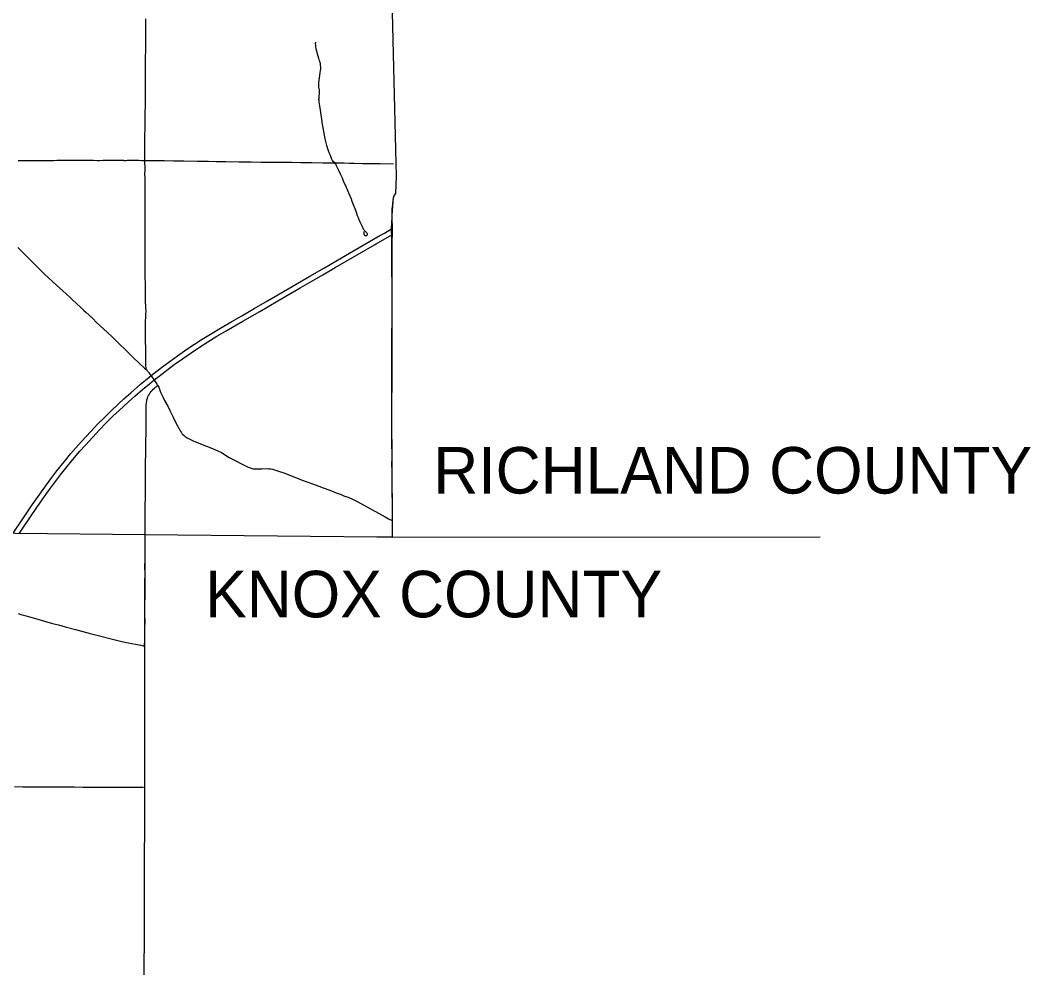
# Model space of a CAD drawing. Extents: x 9078 to 9739, y 4248 to 4966.
# Drawn here: x 9630.7 to 9739.1, y 4597.9 to 4699.7 of the extents above; entities that cross this region are included whole.
import ezdxf

# ---------------------------------------------------------------- set-up
doc = ezdxf.new("R2010")
doc.units = 0
for name, color, linetype in [('GM_X_Adjacent_County', 7, 'Continuous'), ('GM_X_Adjacent_County_Text', 7, 'Continuous'), ('GM_X_County', 7, 'Continuous'), ('GM_X_County_Road', 7, 'Continuous'), ('GM_X_Interstate_Route', 7, 'Continuous'), ('GM_X_Township', 7, 'Continuous'), ('GM_X_Township_Road', 7, 'Continuous')]:
    doc.layers.add(name, color=color, linetype=linetype)

msp = doc.modelspace()

# ---------------------------------------------------------------- linework, layer by layer
at = {"layer": 'GM_X_Adjacent_County'}
msp.add_line((9670.61, 4644.14), (9716.53, 4644.18), dxfattribs=at)
at = {"layer": 'GM_X_County'}
msp.add_lwpolyline([(9670.33, 4710.79), (9670.98, 4684.3), (9671.01, 4682.95), (9670.94, 4681.07), (9670.82, 4680.88), (9670.7, 4680.56), (9670.67, 4680.2), (9670.56, 4678.73), (9670.58, 4676.97), (9670.57, 4675.69), (9670.54, 4657.57), (9670.61, 4645.99), (9670.61, 4644.14), (9668.95, 4644.16), (9644.05, 4644.41), (9644.05, 4642.22), (9644.03, 4632.54), (9644.01, 4617.33), (9643.94, 4593.51)], dxfattribs=at)
at = {"layer": 'GM_X_County_Road'}
for points in [[(9644.29, 4662.08), (9644.26, 4662.12), (9644.23, 4662.19), (9644.2, 4662.27), (9644.19, 4662.36), (9644.17, 4662.52), (9644.15, 4663.02), (9644.16, 4663.43), (9644.16, 4663.92), (9644.15, 4664.41), (9644.11, 4665.23), (9644.11, 4665.64), (9644.12, 4666.05), (9644.14, 4666.71), (9644.14, 4667.03), (9644.17, 4668.08), (9644.18, 4668.4), (9644.16, 4668.81), (9644.12, 4669.55), (9644.12, 4669.88), (9644.12, 4670.29), (9644.13, 4670.78), (9644.12, 4671.44), (9644.1, 4672.01), (9644.1, 4672.58), (9644.08, 4673.49), (9644.08, 4673.99), (9644.09, 4674.72), (9644.09, 4675.13), (9644.1, 4675.86), (9644.1, 4676.85), (9644.1, 4677.26), (9644.08, 4678.08), (9644.08, 4678.49), (9644.08, 4679.06), (9644.09, 4679.39), (9644.09, 4679.63), (9644.08, 4680.28), (9644.08, 4680.53), (9644.07, 4680.94), (9644.07, 4681.26), (9644.08, 4681.69), (9644.07, 4681.99), (9644.07, 4682.42), (9644.07, 4682.74), (9644.06, 4683.09), (9644.07, 4683.56), (9644.07, 4683.96), (9644.06, 4684.29), (9644.06, 4684.61)], [(9645.42, 4660.46), (9645.39, 4660.52), (9645.37, 4660.59), (9645.33, 4660.66), (9645.2, 4660.87), (9645.07, 4661.05), (9645.01, 4661.13), (9644.73, 4661.5), (9644.51, 4661.78), (9644.35, 4661.98), (9644.31, 4662.04), (9644.29, 4662.08)], [(9644.08, 4644.3), (9644.1, 4645.54), (9644.09, 4646.2), (9644.1, 4647.59), (9644.12, 4648.33), (9644.12, 4649.07), (9644.13, 4649.89), (9644.13, 4650.38), (9644.14, 4650.79), (9644.13, 4651.45), (9644.14, 4652.18), (9644.15, 4653.08), (9644.16, 4653.9), (9644.17, 4654.56), (9644.18, 4655.22), (9644.19, 4656.04), (9644.18, 4656.86), (9644.18, 4657.35), (9644.19, 4658.01), (9644.2, 4658.34), (9644.22, 4658.58), (9644.25, 4658.75), (9644.28, 4658.91), (9644.32, 4659.07), (9644.38, 4659.23), (9644.45, 4659.38), (9644.54, 4659.52), (9644.63, 4659.66), (9644.73, 4659.79), (9644.84, 4659.91), (9644.96, 4660.03), (9645.08, 4660.14), (9645.21, 4660.24), (9645.27, 4660.29), (9645.34, 4660.34), (9645.38, 4660.38), (9645.42, 4660.46)], [(9644.03, 4632.46), (9644.04, 4633.11), (9644.04, 4633.76), (9644.06, 4634.49), (9644.07, 4634.98), (9644.06, 4635.88), (9644.06, 4636.62), (9644.06, 4637.44), (9644.06, 4638.74), (9644.06, 4639.23), (9644.07, 4640.29), (9644.06, 4640.95), (9644.07, 4641.77), (9644.07, 4642.34), (9644.08, 4642.99), (9644.08, 4643.81), (9644.08, 4644.3)], [(9630.45, 4635.97), (9630.76, 4635.86), (9631.3, 4635.69), (9632.56, 4635.33), (9633.27, 4635.12), (9634.14, 4634.89), (9634.78, 4634.73), (9635.49, 4634.53), (9636.6, 4634.23), (9637.39, 4634.02), (9638.19, 4633.82), (9639.06, 4633.58), (9640.72, 4633.15), (9641.44, 4632.98), (9642.25, 4632.82), (9643.05, 4632.67), (9643.62, 4632.56), (9644.03, 4632.46)]]:
    msp.add_lwpolyline(points, dxfattribs=at)
at = {"layer": 'GM_X_Interstate_Route'}
for points in [[(9629.92, 4644.59), (9630.96, 4646.12), (9631.97, 4647.62), (9632.95, 4649.03), (9633.48, 4649.77), (9634.07, 4650.56), (9634.62, 4651.27), (9635.44, 4652.29), (9636.12, 4653.12), (9636.65, 4653.74), (9637.25, 4654.41), (9638.25, 4655.5), (9638.98, 4656.27), (9639.67, 4656.98), (9640.37, 4657.66), (9641.21, 4658.46), (9641.81, 4659.01), (9642.55, 4659.66), (9643.6, 4660.57), (9644.3, 4661.15), (9644.73, 4661.5), (9645.06, 4661.77), (9645.84, 4662.37), (9646.76, 4663.05), (9647.56, 4663.63), (9648.57, 4664.33), (9649.39, 4664.88), (9650.22, 4665.41), (9651.26, 4666.06), (9652.11, 4666.56), (9653.39, 4667.3), (9654.45, 4667.92), (9655.8, 4668.7), (9657.22, 4669.52), (9659.42, 4670.8), (9661.76, 4672.16), (9663.32, 4673.07), (9665.16, 4674.14), (9667.5, 4675.5), (9669.28, 4676.53), (9669.78, 4676.81), (9670.54, 4677.25)], [(9668.7, 4675.54), (9668.89, 4675.65), (9670.55, 4676.61)], [(9661.98, 4671.64), (9663.14, 4672.31), (9664.49, 4673.09), (9666.83, 4674.46), (9668.7, 4675.54)], [(9630.6, 4644.58), (9631.03, 4645.21), (9632.45, 4647.32), (9633.1, 4648.26), (9633.72, 4649.14), (9634.35, 4649.99), (9635, 4650.84), (9635.56, 4651.55), (9636.34, 4652.5), (9637.08, 4653.38), (9637.63, 4653.99), (9638.46, 4654.9), (9639.19, 4655.68), (9639.87, 4656.38), (9640.63, 4657.13), (9641.29, 4657.75), (9642.31, 4658.7), (9642.99, 4659.3), (9643.79, 4660), (9644.55, 4660.63), (9645.07, 4661.05), (9645.58, 4661.45), (9646.22, 4661.95), (9647.21, 4662.68), (9648.08, 4663.31), (9649.02, 4663.96), (9649.91, 4664.55), (9650.81, 4665.12), (9651.79, 4665.72), (9652.78, 4666.3), (9654.56, 4667.33), (9656.4, 4668.4), (9658.32, 4669.51), (9660.73, 4670.91), (9661.98, 4671.64)]]:
    msp.add_lwpolyline(points, dxfattribs=at)
at = {"layer": 'GM_X_Township'}
msp.add_lwpolyline([(9644.05, 4644.41), (9630.13, 4644.53), (9617.44, 4644.64), (9617.14, 4644.7), (9600.03, 4645.01), (9585.46, 4645.17), (9576.58, 4645.16)], dxfattribs=at)
at = {"layer": 'GM_X_Township_Road'}
for points in [[(9644.06, 4684.61), (9644.06, 4685.55), (9644.06, 4685.98), (9644.05, 4686.4), (9644.06, 4687.36), (9644.08, 4688.01), (9644.08, 4688.42), (9644.09, 4688.99), (9644.09, 4689.32), (9644.1, 4689.89), (9644.11, 4690.3), (9644.11, 4690.87), (9644.12, 4692.18), (9644.13, 4693.17), (9644.14, 4693.82), (9644.13, 4694.56), (9644.14, 4695.46), (9644.15, 4696.61), (9644.16, 4697.51), (9644.15, 4698.25), (9644.15, 4699.23), (9644.15, 4699.8)], [(9664.43, 4684.34), (9664.28, 4684.49), (9664.2, 4684.6), (9664.09, 4684.82), (9663.96, 4685.12), (9663.87, 4685.35), (9663.75, 4685.65), (9663.64, 4685.96), (9663.57, 4686.2), (9663.53, 4686.36), (9663.42, 4686.92), (9663.34, 4687.32), (9663.26, 4687.72), (9663.18, 4688.12), (9663.13, 4688.45), (9663.08, 4688.77), (9662.98, 4689.5), (9662.92, 4689.99), (9662.83, 4690.48), (9662.77, 4690.88), (9662.75, 4691.04), (9662.74, 4691.14), (9662.75, 4691.25), (9662.77, 4691.53), (9662.8, 4691.78), (9662.81, 4691.94), (9662.8, 4692.1), (9662.78, 4692.17), (9662.72, 4692.48), (9662.72, 4692.73), (9662.73, 4692.89), (9662.73, 4692.97), (9662.75, 4693.22), (9662.78, 4693.46), (9662.82, 4693.71), (9662.88, 4694.03), (9662.92, 4694.27), (9662.93, 4694.44), (9662.93, 4694.6), (9662.91, 4694.85), (9662.89, 4695.01), (9662.87, 4695.09), (9662.82, 4695.25), (9662.77, 4695.4), (9662.72, 4695.55), (9662.65, 4695.79), (9662.58, 4696.02), (9662.54, 4696.18), (9662.45, 4696.57), (9662.41, 4696.81), (9662.39, 4696.97), (9662.38, 4697.13), (9662.39, 4697.29)], [(9630.47, 4684.59), (9630.88, 4684.6), (9631.2, 4684.6), (9631.44, 4684.59), (9631.77, 4684.6), (9632.42, 4684.61), (9632.58, 4684.61), (9632.91, 4684.61), (9633.07, 4684.61), (9633.48, 4684.61), (9633.8, 4684.61), (9634.05, 4684.61), (9634.29, 4684.61), (9634.62, 4684.62), (9634.95, 4684.63), (9635.76, 4684.63), (9636.17, 4684.64), (9636.58, 4684.64), (9636.99, 4684.64), (9638.14, 4684.62), (9638.54, 4684.62), (9638.95, 4684.61), (9639.2, 4684.61), (9639.53, 4684.62), (9639.85, 4684.62), (9640.01, 4684.62), (9640.26, 4684.63), (9640.42, 4684.63), (9640.76, 4684.62), (9641.26, 4684.63), (9641.61, 4684.63), (9641.76, 4684.62), (9641.83, 4684.61), (9641.95, 4684.61), (9642.01, 4684.61), (9642.14, 4684.62), (9642.42, 4684.62), (9643.03, 4684.62), (9643.4, 4684.62), (9643.74, 4684.61), (9643.99, 4684.6), (9644.06, 4684.61)], [(9644.06, 4684.61), (9644.4, 4684.61), (9644.73, 4684.61), (9645.3, 4684.6), (9645.71, 4684.59), (9646.12, 4684.59), (9647.18, 4684.57), (9648.25, 4684.55), (9649.72, 4684.53), (9650.38, 4684.52), (9650.87, 4684.52), (9651.69, 4684.5), (9652.75, 4684.48), (9654.15, 4684.46), (9655.46, 4684.44), (9656.52, 4684.42), (9657.18, 4684.43), (9657.84, 4684.42), (9658.49, 4684.41), (9659.15, 4684.41), (9659.8, 4684.4), (9660.78, 4684.39), (9661.27, 4684.38), (9661.92, 4684.37), (9663.15, 4684.35), (9663.81, 4684.34), (9664.43, 4684.34)], [(9667.57, 4676.99), (9667.57, 4676.86), (9667.56, 4676.78), (9667.57, 4676.7), (9667.58, 4676.66), (9667.6, 4676.62), (9667.62, 4676.59), (9667.66, 4676.56), (9667.71, 4676.54), (9667.76, 4676.53), (9667.8, 4676.53), (9667.84, 4676.54), (9667.87, 4676.56), (9667.9, 4676.59), (9667.91, 4676.62), (9667.93, 4676.65), (9667.94, 4676.69), (9667.93, 4676.73), (9667.91, 4676.77), (9667.87, 4676.84), (9667.82, 4676.9), (9667.69, 4677.01), (9667.64, 4677.07), (9667.58, 4677.13), (9667.54, 4677.2), (9667.5, 4677.27), (9667.47, 4677.33), (9667.4, 4677.47), (9667.34, 4677.62), (9667.27, 4677.77), (9667.17, 4677.99), (9667.1, 4678.14), (9667.07, 4678.21), (9666.98, 4678.44), (9666.89, 4678.67), (9666.81, 4678.9), (9666.69, 4679.21), (9666.46, 4679.82), (9666.31, 4680.2), (9666.22, 4680.43), (9665.97, 4681.03), (9665.68, 4681.71), (9665.38, 4682.39), (9665.25, 4682.69), (9665.04, 4683.13), (9664.88, 4683.51), (9664.67, 4683.96), (9664.6, 4684.11), (9664.57, 4684.18), (9664.52, 4684.25), (9664.43, 4684.34)], [(9664.43, 4684.34), (9665.04, 4684.34), (9665.45, 4684.33), (9666.02, 4684.31), (9666.51, 4684.3), (9667.41, 4684.29), (9667.66, 4684.29), (9667.98, 4684.28), (9668.8, 4684.27), (9669.29, 4684.26), (9670.74, 4684.24)], [(9670.56, 4675.62), (9670.56, 4676), (9670.55, 4676.61), (9670.54, 4676.91), (9670.54, 4677.25), (9670.55, 4677.88), (9670.59, 4678.54), (9670.61, 4679.37), (9670.65, 4679.88), (9670.71, 4680.34), (9670.74, 4680.5)], [(9670.55, 4657.54), (9670.55, 4657.66), (9670.56, 4658.48), (9670.56, 4659.13), (9670.58, 4660.2), (9670.59, 4660.69), (9670.59, 4661.02), (9670.59, 4662.16), (9670.59, 4662.98), (9670.58, 4663.64), (9670.58, 4664.13), (9670.58, 4664.54), (9670.58, 4665.52), (9670.58, 4665.93), (9670.58, 4666.5), (9670.59, 4667.24), (9670.58, 4667.98), (9670.58, 4668.39), (9670.58, 4668.96), (9670.58, 4669.45), (9670.58, 4669.86), (9670.58, 4670.35), (9670.59, 4670.84), (9670.59, 4671.17), (9670.57, 4672.99), (9670.57, 4673.95), (9670.57, 4674.57), (9670.56, 4675.41), (9670.56, 4675.62)], [(9630.42, 4675.25), (9630.71, 4674.97), (9631.34, 4674.32), (9631.64, 4674.04), (9631.87, 4673.81), (9632.22, 4673.46), (9632.85, 4672.82), (9633.32, 4672.36), (9633.68, 4672.03), (9634.22, 4671.54), (9634.58, 4671.2), (9635.24, 4670.59), (9636.03, 4669.88), (9636.33, 4669.6), (9636.69, 4669.26), (9637.23, 4668.76), (9637.47, 4668.54), (9637.71, 4668.31), (9638.07, 4667.98), (9638.49, 4667.59), (9638.83, 4667.25), (9639.24, 4666.84), (9640, 4666.16), (9640.6, 4665.58), (9641.05, 4665.15), (9642.27, 4663.97), (9642.8, 4663.46), (9643.45, 4662.83), (9644.01, 4662.3), (9644.29, 4662.08)], [(9645.42, 4660.46), (9645.54, 4660.25), (9645.75, 4659.73), (9645.87, 4659.43), (9646.01, 4659.13), (9646.16, 4658.84), (9646.51, 4658.2), (9646.74, 4657.76), (9647.1, 4657.03), (9647.43, 4656.36), (9647.73, 4655.78), (9647.85, 4655.57), (9647.94, 4655.43), (9648.03, 4655.3), (9648.14, 4655.17), (9648.26, 4655.06), (9648.38, 4654.96), (9648.59, 4654.82), (9648.73, 4654.73), (9648.87, 4654.66), (9649.25, 4654.49), (9650.01, 4654.19), (9651.3, 4653.66), (9651.97, 4653.37), (9652.27, 4653.23), (9652.56, 4653.07), (9652.83, 4652.89), (9653.11, 4652.72), (9653.83, 4652.33), (9654.41, 4652.02), (9654.85, 4651.8), (9655.15, 4651.67), (9655.38, 4651.58), (9655.53, 4651.54), (9655.69, 4651.5), (9655.86, 4651.49), (9656.1, 4651.48), (9656.59, 4651.49), (9657.17, 4651.51), (9657.41, 4651.5), (9657.58, 4651.48), (9657.74, 4651.45), (9657.97, 4651.39), (9658.29, 4651.28), (9659.06, 4651.01), (9660.05, 4650.63), (9661.05, 4650.25), (9661.43, 4650.1), (9662.27, 4649.79), (9663.19, 4649.45), (9663.89, 4649.19), (9664.57, 4648.92), (9665.11, 4648.72), (9665.49, 4648.57), (9665.88, 4648.43), (9666.41, 4648.21), (9666.56, 4648.14), (9666.92, 4647.95), (9667.63, 4647.55), (9668.27, 4647.19), (9669.21, 4646.68), (9669.85, 4646.32), (9670.21, 4646.13), (9670.59, 4645.95)], [(9670.59, 4645.95), (9670.62, 4646.03), (9670.63, 4646.12), (9670.63, 4646.28), (9670.64, 4646.77), (9670.64, 4647.1), (9670.62, 4647.5), (9670.62, 4648), (9670.6, 4648.73), (9670.59, 4649.71), (9670.58, 4650.45), (9670.58, 4651.27), (9670.57, 4652), (9670.58, 4652.58), (9670.58, 4653.23), (9670.57, 4653.96), (9670.57, 4654.54), (9670.56, 4656.01), (9670.55, 4656.66), (9670.55, 4657.23), (9670.55, 4657.54)], [(9630.06, 4617.37), (9630.96, 4617.36), (9631.78, 4617.35), (9632.35, 4617.35), (9633.67, 4617.34), (9634.24, 4617.34), (9635.31, 4617.34), (9635.96, 4617.33), (9636.45, 4617.33), (9637.43, 4617.32), (9637.86, 4617.32), (9638.18, 4617.32), (9638.58, 4617.32), (9639.16, 4617.32), (9639.89, 4617.31), (9640.71, 4617.3), (9641.21, 4617.3), (9641.7, 4617.3), (9642.27, 4617.3), (9642.93, 4617.3), (9643.9, 4617.29)]]:
    msp.add_lwpolyline(points, dxfattribs=at)

# ---------------------------------------------------------------- texts
at = {"layer": 'GM_X_Adjacent_County_Text'}
for s, p in [('RICHLAND COUNTY', (9675.01, 4648.83)), ('KNOX COUNTY', (9650.53, 4635.54))]:
    msp.add_text(s, height=5, dxfattribs=at).set_placement(p)

doc.saveas('drawing.dxf')
